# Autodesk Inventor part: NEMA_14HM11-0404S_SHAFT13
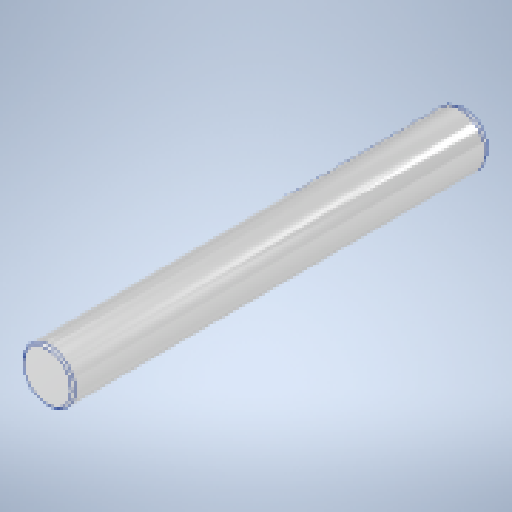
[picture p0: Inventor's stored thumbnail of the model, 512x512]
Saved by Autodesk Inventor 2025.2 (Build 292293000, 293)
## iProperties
Created: 2019-11
Part Number: NEMA_14HM11-0404S_SHAFT13
Material: Générique
Document SubType Name: Modeling
Designer: thoma
Density: 1 g/cm^3
Appearance: Aluminium - Plat
Author: thoma
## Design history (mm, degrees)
sketch "Esquisse1"
  geometry: C1 r 2.5 at (0, 0); 1 further point
  constraints: 1 centre point, 1 coincident
  dimensions: "d0" = 5 diameter of C1
extrude "Extrusion1" new body sketch "Esquisse1" distance "d1" = 40; taper "d2" = 0 deg
chamfer "Chanfrein1" distance "d3" = 0.2; stored, may be unused: second distance "d4" = 2, angle "d5" = 45 deg
chamfer "Chanfrein2" distance "d6" = 0.3; stored, may be unused: second distance "d7" = 2, angle "d8" = 60 deg
sketch "Esquisse2"
  geometry: L1 (-2.5, 0)-(2, 0); L2 (2, 0)-(2, 1.5); L3 (2, 0)-(2, -1.5); A1 r 2.5 centre (0, 0) between (2, -1.5) and (2, 1.5); 2 further points
  constraints: 6 end point, 2 point on circle, 1 centre point, 1 coincident, 1 horizontal, 1 horizontal alignment, 1 point on line, 1 vertical, 1 other
  dimensions: "d9" = 4.5 distance of L1.start L1.end
extrude "Extrusion2" cut sketch "Esquisse2" distance "d10" = 15; taper "d11" = 0 deg
fillet "Congé1" dims "d12" = 0.1
node "Solide1"
